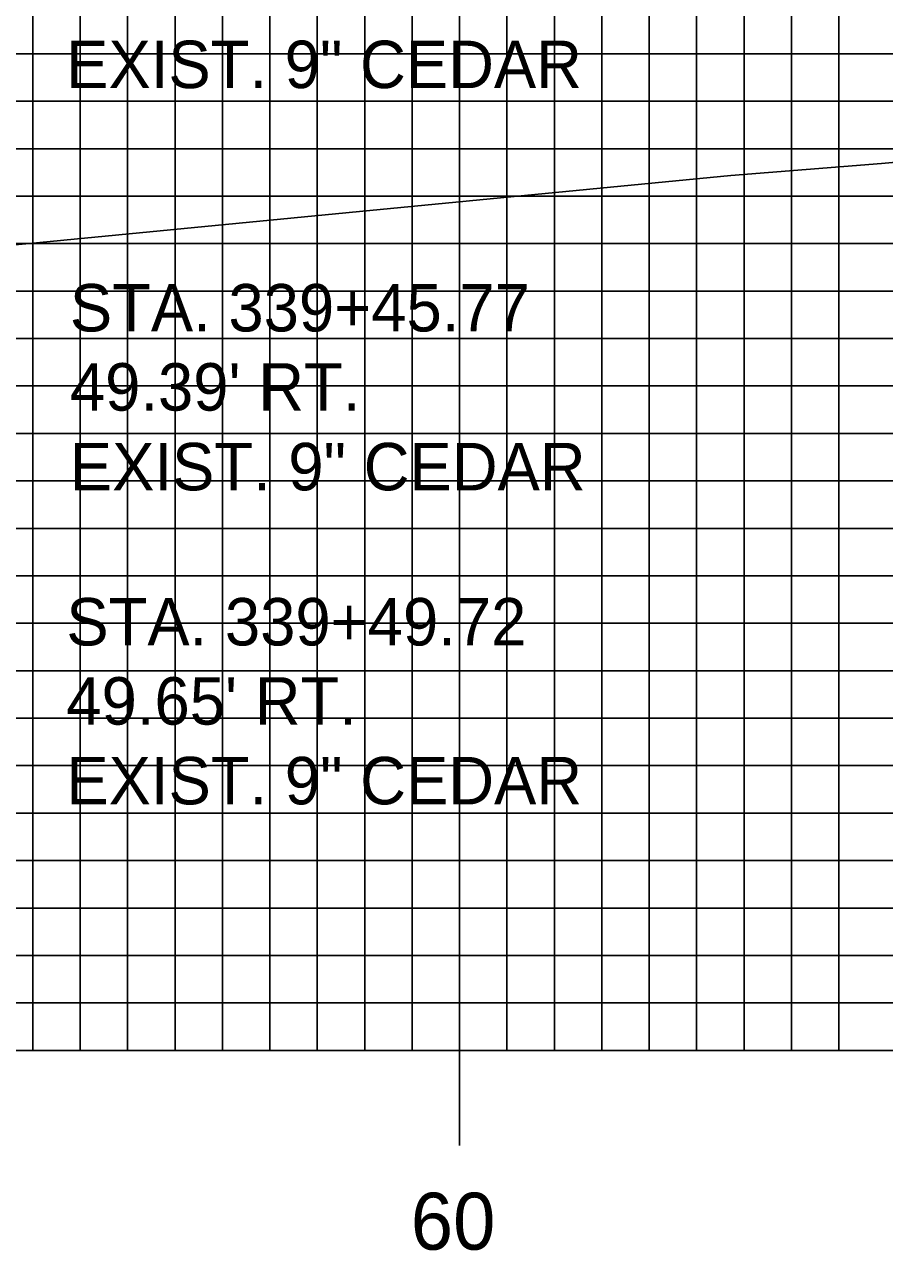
# Model space of a CAD drawing. Extents: x 1824360 to 1824703, y 442591 to 442811.
# Drawn here: x 1824576.16 to 1824594.3, y 442649.45 to 442675.28 of the extents above; entities that cross this region are included whole.
import ezdxf

# ---------------------------------------------------------------- set-up
doc = ezdxf.new("R2010")
doc.units = 0
for name, color, linetype in [('D_Text_Monospaced', 7, 'Continuous'), ('H_V ANNOTATION', 7, 'Continuous'), ('MAJOR', 7, 'Continuous'), ('MINOR', 7, 'Continuous'), ('S_Roadway_Centerline', 7, 'Continuous')]:
    doc.layers.add(name, color=color, linetype=linetype)

msp = doc.modelspace()

# ---------------------------------------------------------------- linework, layer by layer
at = {"layer": 'MAJOR'}
for p, q in [((1824585.335, 442653.665), (1824585.335, 442683.665)), ((1824385.335, 442673.665), (1824665.335, 442673.665)), ((1824385.335, 442668.665), (1824665.335, 442668.665)), ((1824385.335, 442663.665), (1824665.335, 442663.665)), ((1824385.335, 442658.665), (1824665.335, 442658.665)), ((1824385.335, 442653.665), (1824665.335, 442653.665)), ((1824385.335, 442653.665), (1824665.335, 442653.665)), ((1824585.335, 442651.661), (1824585.335, 442653.665))]:
    msp.add_line(p, q, dxfattribs=at)
at = {"layer": 'MINOR'}
for p, q in [((1824576.335, 442653.665), (1824576.335, 442683.665)), ((1824577.335, 442653.665), (1824577.335, 442683.665)), ((1824578.335, 442653.665), (1824578.335, 442683.665)), ((1824579.335, 442653.665), (1824579.335, 442683.665)), ((1824580.335, 442653.665), (1824580.335, 442683.665)), ((1824581.335, 442653.665), (1824581.335, 442683.665)), ((1824582.335, 442653.665), (1824582.335, 442683.665)), ((1824583.335, 442653.665), (1824583.335, 442683.665)), ((1824584.335, 442653.665), (1824584.335, 442683.665)), ((1824586.335, 442653.665), (1824586.335, 442683.665)), ((1824587.335, 442653.665), (1824587.335, 442683.665)), ((1824588.335, 442653.665), (1824588.335, 442683.665)), ((1824589.335, 442653.665), (1824589.335, 442683.665)), ((1824590.335, 442653.665), (1824590.335, 442683.665)), ((1824591.335, 442653.665), (1824591.335, 442683.665)), ((1824592.335, 442653.665), (1824592.335, 442683.665)), ((1824593.335, 442653.665), (1824593.335, 442683.665)), ((1824385.335, 442674.665), (1824665.335, 442674.665)), ((1824385.335, 442672.665), (1824665.335, 442672.665)), ((1824385.335, 442671.665), (1824665.335, 442671.665)), ((1824385.335, 442670.665), (1824665.335, 442670.665)), ((1824385.335, 442669.665), (1824665.335, 442669.665)), ((1824385.335, 442667.665), (1824665.335, 442667.665)), ((1824385.335, 442666.665), (1824665.335, 442666.665)), ((1824385.335, 442665.665), (1824665.335, 442665.665)), ((1824385.335, 442664.665), (1824665.335, 442664.665)), ((1824385.335, 442662.665), (1824665.335, 442662.665)), ((1824385.335, 442661.665), (1824665.335, 442661.665)), ((1824385.335, 442660.665), (1824665.335, 442660.665)), ((1824385.335, 442659.665), (1824665.335, 442659.665)), ((1824385.335, 442657.665), (1824665.335, 442657.665)), ((1824385.335, 442656.665), (1824665.335, 442656.665)), ((1824385.335, 442655.665), (1824665.335, 442655.665)), ((1824385.335, 442654.665), (1824665.335, 442654.665))]:
    msp.add_line(p, q, dxfattribs=at)
at = {"layer": 'S_Roadway_Centerline'}
msp.add_lwpolyline([(1824510.764, 442669.859), (1824519.18, 442670.249), (1824522.079, 442670.426), (1824525.261, 442670.355), (1824532.064, 442670.384), (1824535.378, 442670.469), (1824541.4, 442670.335), (1824542.121, 442670.312), (1824542.458, 442670.315), (1824542.491, 442670.319), (1824542.977, 442670.338), (1824545.548, 442670.251), (1824548.755, 442669.568), (1824552.816, 442668.477), (1824556.938, 442668.751), (1824559.063, 442668.996), (1824559.273, 442669.03), (1824562.836, 442669.432), (1824565.983, 442669.754), (1824572.676, 442670.341), (1824576.264, 442670.67), (1824591.059, 442672.098), (1824594.234, 442672.354), (1824601.122, 442672.986)], dxfattribs=at)

# ---------------------------------------------------------------- texts
at = {"layer": 'D_Text_Monospaced'}
for s, height, p in [('EXIST. 9" CEDAR', 0.99996, (1824577.04, 442673.942)), ('STA. 339+45.77', 0.99996, (1824577.117, 442668.814)), ("49.39' RT.", 1, (1824577.117, 442667.146)), ('EXIST. 9" CEDAR', 0.99996, (1824577.117, 442665.466)), ('STA. 339+49.72', 0.99996, (1824577.043, 442662.197)), ("49.65' RT.", 1, (1824577.043, 442660.529)), ('EXIST. 9" CEDAR', 0.99996, (1824577.043, 442658.849))]:
    msp.add_text(s, height=height, dxfattribs=at).set_placement(p)
at = {"layer": 'H_V ANNOTATION'}
msp.add_text('60', height=1.2, dxfattribs=at).set_placement((1824584.307, 442649.465))

doc.saveas('drawing.dxf')
